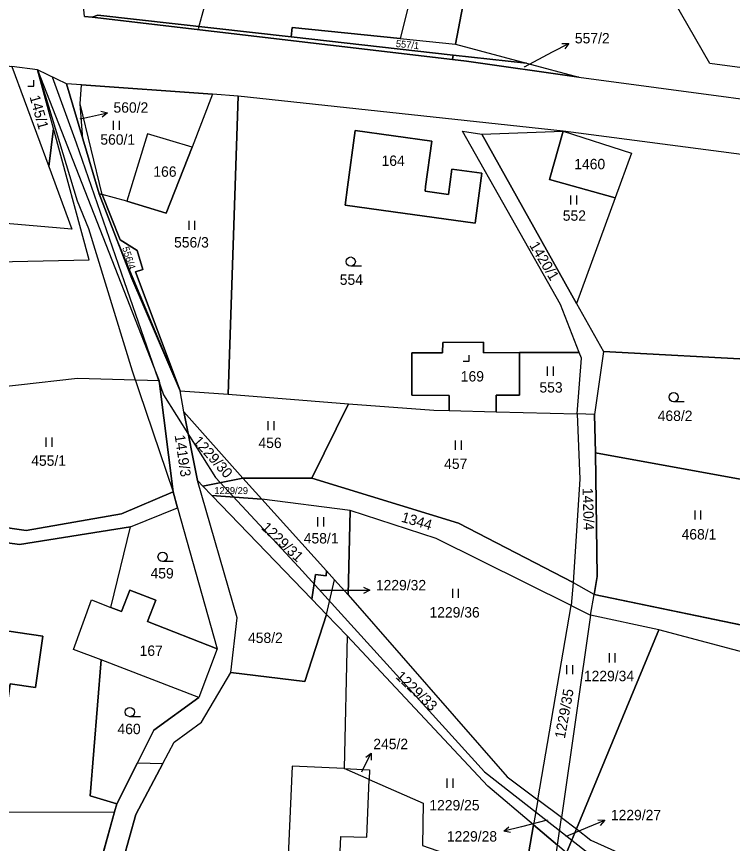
# Model space of a CAD drawing. Extents: x -588699 to -585793, y -1060280 to -1056731.
# Drawn here: x -586946 to -586828.9, y -1058685.8 to -1058550.5 of the extents above; entities that cross this region are included whole.
import ezdxf

# ---------------------------------------------------------------- set-up
doc = ezdxf.new("R2010")
doc.units = 0
for name, color, linetype in [('Druh pozemku', 7, 'Continuous'), ('Lesy', 7, 'Continuous'), ('Parcela nároku', 7, 'Continuous'), ('Parcelní číslo', 7, 'Continuous'), ('Vnitřní obvod', 7, 'Continuous')]:
    doc.layers.add(name, color=color, linetype=linetype)

msp = doc.modelspace()

# ---------------------------------------------------------------- linework, layer by layer
at = {"layer": 'Druh pozemku'}
for p, q in [((-586930.2, -1058567.55), (-586930.2, -1058569.05)), ((-586929.18, -1058569.05), (-586929.18, -1058567.55)), ((-586855.37, -1058579.77), (-586855.37, -1058581.27)), ((-586854.34, -1058581.27), (-586854.34, -1058579.77)), ((-586917.83, -1058583.91), (-586917.83, -1058585.41)), ((-586916.81, -1058585.41), (-586916.81, -1058583.91)), ((-586889.57, -1058591.35), (-586891.32, -1058591.35)), ((-586859.16, -1058607.79), (-586859.16, -1058609.29)), ((-586858.14, -1058609.29), (-586858.14, -1058607.79)), ((-586836.75, -1058613.54), (-586838.5, -1058613.54)), ((-586904.89, -1058616.72), (-586904.89, -1058618.22)), ((-586903.86, -1058618.22), (-586903.86, -1058616.72)), ((-586941.23, -1058619.41), (-586941.23, -1058620.91)), ((-586940.2, -1058620.91), (-586940.2, -1058619.41)), ((-586874.25, -1058619.9), (-586874.25, -1058621.4)), ((-586873.22, -1058621.4), (-586873.22, -1058619.9)), ((-586835.04, -1058631.34), (-586835.04, -1058632.84)), ((-586834.02, -1058632.84), (-586834.02, -1058631.34)), ((-586896.77, -1058632.46), (-586896.77, -1058633.96)), ((-586895.74, -1058633.96), (-586895.74, -1058632.46)), ((-586920.36, -1058639.67), (-586922.11, -1058639.67)), ((-586874.7, -1058644.16), (-586874.7, -1058645.66)), ((-586873.68, -1058645.66), (-586873.68, -1058644.16)), ((-586849.06, -1058654.71), (-586849.06, -1058656.21)), ((-586848.04, -1058656.21), (-586848.04, -1058654.71)), ((-586856.01, -1058656.65), (-586856.01, -1058658.15)), ((-586854.98, -1058658.15), (-586854.98, -1058656.65)), ((-586925.72, -1058665.09), (-586927.47, -1058665.09)), ((-586875.6, -1058675.22), (-586875.6, -1058676.72)), ((-586874.58, -1058676.72), (-586874.58, -1058675.22))]:
    msp.add_line(p, q, dxfattribs=at)
for points in [[(-586944.16, -1058561.89), (-586943.16, -1058561.89), (-586943.16, -1058560.89)], [(-586872.92, -1058606.9), (-586871.92, -1058606.9), (-586871.92, -1058605.9)]]:
    msp.add_lwpolyline(points, dxfattribs=at)
for centre in [(-586891.32, -1058590.6), (-586838.5, -1058612.79), (-586922.11, -1058638.92), (-586927.47, -1058664.34)]:
    msp.add_circle(centre, 0.75, dxfattribs=at)
at = {"layer": 'Lesy'}
for p, q in [((-586937.84, -1058561.49), (-586942.57, -1058559.22)), ((-586932.48, -1058579.51), (-586935.16, -1058570.5)), ((-586929.81, -1058586.43), (-586932.48, -1058579.51)), ((-586934.24, -1058585.2), (-586927.07, -1058608.49)), ((-586919.25, -1058611.77), (-586929.81, -1058586.43)), ((-586927.07, -1058608.49), (-586920.38, -1058628.31)), ((-586918.62, -1058615.19), (-586919.25, -1058611.77)), ((-586909, -1058626.06), (-586918.62, -1058615.19)), ((-586897.7, -1058626.06), (-586909, -1058626.06)), ((-586873.71, -1058633.44), (-586897.7, -1058626.06)), ((-586920.38, -1058628.31), (-586919.65, -1058630.91)), ((-586919.65, -1058630.91), (-586913.16, -1058653.98)), ((-586855.25, -1058642.98), (-586873.71, -1058633.44)), ((-586851.48, -1058645.09), (-586855.25, -1058642.98)), ((-586817.65, -1058652.11), (-586851.48, -1058645.09)), ((-586913.16, -1058653.98), (-586916.18, -1058661.96)), ((-586916.18, -1058661.96), (-586923.52, -1058667.3)), ((-586923.52, -1058667.3), (-586926.22, -1058672.66)), ((-586926.22, -1058672.66), (-586929.59, -1058679.33)), ((-586929.59, -1058679.33), (-586929.95, -1058680.64)), ((-586929.95, -1058680.64), (-586935.97, -1058702.25))]:
    msp.add_line(p, q, dxfattribs=at)
for points in [[(-586942.57, -1058559.22), (-586936.11, -1058580.67), (-586934.24, -1058585.2)], [(-586935.16, -1058570.5), (-586935.57, -1058564.8), (-586935.4, -1058561.66), (-586937.84, -1058561.49)]]:
    msp.add_lwpolyline(points, dxfattribs=at)
at = {"layer": 'Parcela nároku'}
for points in [[(-586935.39, -1058545.43), (-586930.16, -1058501.68), (-586916.68, -1058504.17), (-586904.54, -1058509.26), (-586892.17, -1058517.22), (-586875.35, -1058522.58), (-586883.25, -1058554.1), (-586900.89, -1058552.29), (-586901.09, -1058553.82), (-586932.71, -1058550.27), (-586933.62, -1058550.62), (-586934.89, -1058550.47)], [(-586869.14, -1058528.69), (-586875.35, -1058522.58), (-586883.25, -1058554.1), (-586874.19, -1058555.03)], [(-586871.4, -1058523.77), (-586875.35, -1058522.58), (-586869.14, -1058528.69), (-586874.19, -1058555.03), (-586862.54, -1058558.15), (-586854.02, -1058560.42), (-586804.23, -1058567.06), (-586807.28, -1058561.54), (-586832.56, -1058558.16), (-586845.52, -1058535.63), (-586863.45, -1058526.16)], [(-586845.52, -1058535.63), (-586838.02, -1058539.59), (-586814.5, -1058548.51), (-586807.28, -1058561.54), (-586832.56, -1058558.16)], [(-586901.09, -1058553.82), (-586874.54, -1058556.8), (-586874.68, -1058557.5), (-586933.62, -1058550.62), (-586932.71, -1058550.27)], [(-586883.25, -1058554.1), (-586874.19, -1058555.03), (-586862.54, -1058558.15), (-586874.54, -1058556.8), (-586901.09, -1058553.82), (-586900.89, -1058552.29)], [(-586982.64, -1058555.63), (-586983.76, -1058577.52), (-586984.31, -1058591.39), (-586934.1, -1058590.3), (-586939.95, -1058568.84), (-586940.74, -1058575.03), (-586936.96, -1058585.27), (-586967.4, -1058582.66), (-586965.22, -1058556.24), (-586979.1, -1058554.41)], [(-586940.74, -1058575.03), (-586936.96, -1058585.27), (-586967.4, -1058582.66), (-586965.22, -1058556.24), (-586946.78, -1058558.67)], [(-586874.54, -1058556.8), (-586862.54, -1058558.15), (-586854.02, -1058560.42), (-586872.37, -1058557.77), (-586874.68, -1058557.5)], [(-586996.63, -1058616.02), (-586984.31, -1058591.39), (-586934.1, -1058590.3), (-586939.95, -1058568.84), (-586942.57, -1058559.22), (-586922.66, -1058610.11), (-586936.01, -1058609.72), (-586955.38, -1058611.93), (-586955.53, -1058604.84), (-586975.52, -1058605.27), (-586975.17, -1058621.7), (-586987.28, -1058624.4)], [(-586939.95, -1058568.84), (-586942.57, -1058559.22), (-586946.78, -1058558.67), (-586940.74, -1058575.03)], [(-586937.84, -1058561.49), (-586942.57, -1058559.22), (-586922.66, -1058610.11), (-586920.38, -1058628.31), (-586919.65, -1058630.91), (-586913.16, -1058653.98), (-586916.18, -1058661.96), (-586923.52, -1058667.3), (-586926.22, -1058672.66), (-586922.07, -1058672.74), (-586920.21, -1058669.24), (-586915.73, -1058666.01), (-586910.92, -1058657.87), (-586909.93, -1058648.91), (-586916.41, -1058626.46), (-586918.62, -1058615.19), (-586919.25, -1058611.77), (-586927.14, -1058593.35), (-586932.48, -1058579.51)], [(-586931.97, -1058579.64), (-586935.57, -1058564.8), (-586935.4, -1058561.66), (-586937.84, -1058561.49), (-586932.48, -1058579.51)], [(-586935.57, -1058564.8), (-586935.4, -1058561.66), (-586913.94, -1058563.18), (-586917.29, -1058571.85), (-586924.56, -1058569.67), (-586927.97, -1058580.71), (-586931.97, -1058579.64)], [(-586909.75, -1058563.5), (-586913.94, -1058563.18), (-586917.29, -1058571.85), (-586921.5, -1058582.69), (-586927.97, -1058580.71), (-586931.97, -1058579.64), (-586929.05, -1058587.03), (-586926.29, -1058588.8), (-586925.34, -1058591.91), (-586926.52, -1058592.27), (-586919.25, -1058611.77), (-586911.39, -1058612.32)], [(-586881.31, -1058612.49), (-586881.32, -1058605.54), (-586876.29, -1058605.53), (-586876.28, -1058603.82), (-586869.61, -1058603.81), (-586869.61, -1058605.51), (-586863.69, -1058605.5), (-586853.93, -1058605.48), (-586857.02, -1058597.61), (-586873.05, -1058569.24), (-586869.85, -1058569.74), (-586856.59, -1058569.23), (-586909.75, -1058563.5), (-586911.39, -1058612.32), (-586891.71, -1058613.89), (-586877.73, -1058614.93), (-586875.22, -1058614.99), (-586875.23, -1058612.52)], [(-586891.86, -1058578.43), (-586890.62, -1058569.15), (-586878.07, -1058570.88), (-586879.09, -1058578.3), (-586879.17, -1058579.09), (-586875.33, -1058579.6), (-586874.78, -1058575.49), (-586869.86, -1058576.15), (-586870.95, -1058584.3), (-586884.39, -1058582.45), (-586892.23, -1058581.36)], [(-586870.95, -1058584.3), (-586869.86, -1058576.15), (-586874.78, -1058575.49), (-586875.33, -1058579.6), (-586879.17, -1058579.09), (-586879.09, -1058578.3), (-586878.07, -1058570.88), (-586890.62, -1058569.15), (-586891.86, -1058578.43), (-586892.23, -1058581.36), (-586884.39, -1058582.45)], [(-586917.29, -1058571.85), (-586924.56, -1058569.67), (-586927.97, -1058580.71), (-586921.5, -1058582.69)], [(-586854.25, -1058615.51), (-586853.56, -1058606.42), (-586853.93, -1058605.48), (-586857.02, -1058597.61), (-586873.05, -1058569.24), (-586869.85, -1058569.74), (-586854.38, -1058597.45), (-586849.98, -1058605.33), (-586851.42, -1058615.61)], [(-586858.8, -1058577.17), (-586848.05, -1058580.18), (-586854.38, -1058597.45), (-586869.85, -1058569.74), (-586856.59, -1058569.23)], [(-586856.59, -1058569.23), (-586845.36, -1058572.84), (-586848.05, -1058580.18), (-586858.8, -1058577.17)], [(-586848.05, -1058580.18), (-586854.38, -1058597.45), (-586849.98, -1058605.33), (-586823.61, -1058606.72), (-586816.91, -1058607.07), (-586816.4, -1058604.52), (-586811.36, -1058605.37), (-586811.07, -1058603.41), (-586802.46, -1058605.29), (-586803.06, -1058608.62), (-586800.23, -1058609.18), (-586797.12, -1058609.8), (-586796.17, -1058600.31), (-586795.7, -1058577.24), (-586856.59, -1058569.23), (-586845.36, -1058572.84)], [(-586919.25, -1058611.77), (-586926.52, -1058592.27), (-586925.34, -1058591.91), (-586926.29, -1058588.8), (-586929.05, -1058587.03), (-586931.97, -1058579.64), (-586932.48, -1058579.51), (-586927.14, -1058593.35)], [(-586876.29, -1058605.53), (-586881.32, -1058605.54), (-586881.31, -1058612.49), (-586875.23, -1058612.52), (-586875.22, -1058614.99), (-586867.52, -1058615.18), (-586867.54, -1058612.49), (-586863.69, -1058612.49), (-586863.69, -1058605.5), (-586869.61, -1058605.51), (-586869.61, -1058603.81), (-586876.28, -1058603.82)], [(-586863.69, -1058612.49), (-586867.54, -1058612.49), (-586867.52, -1058615.18), (-586854.25, -1058615.51), (-586853.56, -1058606.42), (-586853.93, -1058605.48), (-586863.69, -1058605.5)], [(-586823.61, -1058606.72), (-586849.98, -1058605.33), (-586851.42, -1058615.61), (-586851.29, -1058621.89), (-586822.19, -1058627.19), (-586821.69, -1058624.31), (-586810.47, -1058626.19), (-586810.97, -1058629.24), (-586800.47, -1058631.15), (-586798.62, -1058625.12), (-586825.01, -1058620.48)], [(-586955.1, -1058624.84), (-586975.09, -1058625.27), (-586975.17, -1058621.7), (-586987.28, -1058624.4), (-586974.32, -1058630.3), (-586944.43, -1058634.63), (-586928.81, -1058631.9), (-586920.38, -1058628.31), (-586922.66, -1058610.11), (-586936.01, -1058609.72), (-586955.38, -1058611.93)], [(-586911.39, -1058612.32), (-586891.71, -1058613.89), (-586897.7, -1058626.06), (-586909, -1058626.06), (-586918.62, -1058615.19), (-586919.25, -1058611.77)], [(-586909, -1058626.06), (-586918.62, -1058615.19), (-586916.41, -1058626.46), (-586915.52, -1058627.37)], [(-586891.71, -1058613.89), (-586877.73, -1058614.93), (-586875.22, -1058614.99), (-586867.52, -1058615.18), (-586854.25, -1058615.51), (-586853.82, -1058626.21), (-586854.92, -1058643.12), (-586873.71, -1058633.44), (-586897.7, -1058626.06)], [(-586944.43, -1058634.63), (-586974.32, -1058630.3), (-586987.28, -1058624.4), (-586996.63, -1058616.02), (-586997.71, -1058618.13), (-586988.17, -1058626.9), (-586973.23, -1058633.1), (-586945.54, -1058636.92), (-586927.38, -1058634.01), (-586919.65, -1058630.91), (-586920.38, -1058628.31), (-586928.81, -1058631.9)], [(-586851.29, -1058621.89), (-586851.42, -1058615.61), (-586854.25, -1058615.51), (-586853.82, -1058626.21), (-586854.92, -1058643.12), (-586855.24, -1058646.91), (-586852.11, -1058648.46), (-586851.48, -1058645.09), (-586851.01, -1058642.14)], [(-586822.19, -1058627.19), (-586851.29, -1058621.89), (-586851.01, -1058642.14), (-586851.48, -1058645.09), (-586817.65, -1058652.11), (-586805.15, -1058658.88), (-586801.97, -1058646.29), (-586801.14, -1058637.92), (-586800.47, -1058631.15), (-586810.97, -1058629.24), (-586812.33, -1058637.49), (-586818.79, -1058636.38), (-586817.95, -1058631.53), (-586822.8, -1058630.72)], [(-586897.67, -1058645.88), (-586895.29, -1058648.35), (-586898.83, -1058659.35), (-586910.92, -1058657.87), (-586909.93, -1058648.91), (-586916.41, -1058626.46), (-586915.52, -1058627.37), (-586914.05, -1058628.88)], [(-586905.89, -1058629.51), (-586909, -1058626.06), (-586915.52, -1058627.37), (-586914.05, -1058628.88)], [(-586897.7, -1058626.06), (-586873.71, -1058633.44), (-586854.92, -1058643.12), (-586855.24, -1058646.91), (-586877.37, -1058635.92), (-586891.44, -1058631.37), (-586905.89, -1058629.51), (-586909, -1058626.06)], [(-586895.31, -1058641.23), (-586905.89, -1058629.51), (-586914.05, -1058628.88), (-586897.67, -1058645.88), (-586897.09, -1058641.82), (-586895.37, -1058642.04)], [(-586891.44, -1058631.37), (-586905.89, -1058629.51), (-586895.31, -1058641.23), (-586893.99, -1058642.68), (-586891.75, -1058645.16)], [(-586924.55, -1058649.53), (-586923.22, -1058646.04), (-586927.48, -1058644.38), (-586928.82, -1058647.87), (-586930.55, -1058647.2), (-586927.38, -1058634.01), (-586919.65, -1058630.91), (-586913.16, -1058653.98)], [(-586877.37, -1058635.92), (-586891.44, -1058631.37), (-586891.75, -1058645.16), (-586865.74, -1058674.93), (-586860.73, -1058678.68), (-586855.24, -1058646.91)], [(-586932.16, -1058655.81), (-586936.67, -1058654.08), (-586933.73, -1058645.96), (-586930.55, -1058647.2), (-586927.38, -1058634.01), (-586945.54, -1058636.92), (-586973.23, -1058633.1), (-586982.68, -1058632.84), (-586977.96, -1058666.11), (-586973.22, -1058680.8), (-586929.95, -1058680.64), (-586929.59, -1058679.33), (-586933.94, -1058678.03)], [(-586895.31, -1058641.23), (-586895.37, -1058642.04), (-586897.09, -1058641.82), (-586897.67, -1058645.88), (-586895.29, -1058648.35), (-586893.99, -1058642.68)], [(-586893.99, -1058642.68), (-586891.75, -1058645.16), (-586865.74, -1058674.93), (-586860.73, -1058678.68), (-586861.44, -1058682.79), (-586868.9, -1058676.45), (-586891.9, -1058651.87), (-586895.29, -1058648.35)], [(-586933.73, -1058645.96), (-586930.55, -1058647.2), (-586928.82, -1058647.87), (-586927.48, -1058644.38), (-586923.22, -1058646.04), (-586924.55, -1058649.53), (-586913.16, -1058653.98), (-586916.18, -1058661.96), (-586932.16, -1058655.81), (-586936.67, -1058654.08)], [(-586851.48, -1058645.09), (-586817.65, -1058652.11), (-586805.15, -1058658.88), (-586791.48, -1058671.6), (-586792.77, -1058674.76), (-586796.81, -1058672.17), (-586805.63, -1058662.11), (-586816.72, -1058657.34), (-586840.89, -1058650.86), (-586852.11, -1058648.46)], [(-586855.24, -1058646.91), (-586852.11, -1058648.46), (-586856.86, -1058681.59), (-586860.73, -1058678.68)], [(-586840.89, -1058650.86), (-586852.11, -1058648.46), (-586856.86, -1058681.59), (-586854.39, -1058683.44)], [(-586945.81, -1058651.29), (-586941.68, -1058651.91), (-586942.92, -1058660.31), (-586947.04, -1058659.71), (-586948.86, -1058672.19), (-586958.77, -1058670.94), (-586955.67, -1058649.84)], [(-586958.77, -1058670.94), (-586948.86, -1058672.19), (-586947.04, -1058659.71), (-586942.92, -1058660.31), (-586941.68, -1058651.91), (-586945.81, -1058651.29), (-586955.67, -1058649.84)], [(-586805.63, -1058662.11), (-586816.72, -1058657.34), (-586840.89, -1058650.86), (-586854.39, -1058683.44), (-586852.02, -1058685.29), (-586820.88, -1058699.32), (-586805.39, -1058705.78), (-586803.87, -1058706.44), (-586802.96, -1058699.63), (-586799.98, -1058686.35), (-586796.81, -1058672.17)], [(-586868.9, -1058676.45), (-586891.9, -1058651.87), (-586892.4, -1058673.58), (-586888.23, -1058673.81), (-586888.3, -1058675.38), (-586879.46, -1058679.27), (-586879.6, -1058686.15), (-586863.03, -1058691.98), (-586861.44, -1058682.79)], [(-586916.18, -1058661.96), (-586932.16, -1058655.81), (-586933.94, -1058678.03), (-586929.59, -1058679.33), (-586926.22, -1058672.66), (-586923.52, -1058667.3)], [(-586938.93, -1058736.17), (-586935.97, -1058702.25), (-586929.95, -1058680.64), (-586929.59, -1058679.33), (-586926.22, -1058672.66), (-586922.07, -1058672.74), (-586926.49, -1058681.08), (-586932.68, -1058703.36), (-586934.27, -1058720.98), (-586935.76, -1058737.71), (-586941.82, -1058775.73), (-586945.72, -1058787.88), (-586948.79, -1058785.05), (-586945.33, -1058774.96)], [(-586903.15, -1058691.48), (-586903.25, -1058693.43), (-586901.8, -1058693.5), (-586903.2, -1058722.75), (-586894.83, -1058723.27), (-586893.4, -1058694), (-586891.88, -1058693.96), (-586891.79, -1058692.15), (-586893.26, -1058692.06), (-586892.92, -1058684.68), (-586888.69, -1058684.79), (-586888.3, -1058675.38), (-586892.4, -1058673.58), (-586900.9, -1058673.18), (-586901.71, -1058691.55)], [(-586892.4, -1058673.58), (-586888.23, -1058673.81), (-586888.3, -1058675.38)], [(-586860.73, -1058678.68), (-586861.44, -1058682.79), (-586857.51, -1058686.13), (-586856.86, -1058681.59)], [(-586973.22, -1058680.8), (-586929.95, -1058680.64), (-586935.97, -1058702.25), (-586938.93, -1058736.17), (-586955.56, -1058735.53)], [(-586861.44, -1058682.79), (-586863.03, -1058691.98), (-586858.58, -1058693.54), (-586857.51, -1058686.13)], [(-586857.51, -1058686.13), (-586856.86, -1058681.59), (-586854.39, -1058683.44), (-586856.03, -1058687.39)], [(-586854.39, -1058683.44), (-586852.02, -1058685.29), (-586820.88, -1058699.32), (-586805.39, -1058705.78), (-586803.87, -1058706.44), (-586804.7, -1058712.59), (-586808.72, -1058710.56), (-586853.81, -1058689.27), (-586856.03, -1058687.39)]]:
    msp.add_lwpolyline(points, close=True, dxfattribs=at)
for points in [[(-586934.89, -1058550.47), (-586933.62, -1058550.62), (-586874.68, -1058557.5), (-586872.37, -1058557.77), (-586854.02, -1058560.42), (-586804.23, -1058567.06), (-586803.05, -1058567.22), (-586798.16, -1058567.87), (-586687.14, -1058583.77), (-586665.54, -1058591.33), (-586602.99, -1058626.52)], [(-586618.94, -1058628.76), (-586660.99, -1058605.82), (-586679.22, -1058595.88), (-586690.29, -1058590.65), (-586705.65, -1058589.53), (-586716.68, -1058588.73), (-586716.99, -1058590.88), (-586735.61, -1058587.36), (-586740.23, -1058586.48), (-586755.16, -1058583.44), (-586759.61, -1058582.79), (-586774.79, -1058579.98), (-586795.7, -1058577.24), (-586856.59, -1058569.23), (-586909.75, -1058563.5), (-586913.94, -1058563.18), (-586935.4, -1058561.66), (-586937.84, -1058561.49), (-586942.57, -1058559.22), (-586946.78, -1058558.67)], [(-586932.68, -1058703.36), (-586926.49, -1058681.08), (-586922.07, -1058672.74), (-586920.21, -1058669.24), (-586915.73, -1058666.01), (-586910.92, -1058657.87), (-586898.83, -1058659.35), (-586895.29, -1058648.35), (-586891.9, -1058651.87), (-586892.4, -1058673.58), (-586900.9, -1058673.18), (-586901.71, -1058691.55)], [(-586893.26, -1058692.06), (-586892.92, -1058684.68), (-586888.69, -1058684.79), (-586888.3, -1058675.38), (-586879.46, -1058679.27), (-586879.6, -1058686.15)]]:
    msp.add_lwpolyline(points, dxfattribs=at)
at = {"layer": 'Parcelní číslo'}
for p, q in [((-586916.21, -1058552.46), (-586915.3, -1058549.05)), ((-586858.3, -1058556.29), (-586855.65, -1058554.89)), ((-586862.87, -1058558.71), (-586858.3, -1058556.29)), ((-586934.06, -1058566.9), (-586931.14, -1058566.23)), ((-586935.58, -1058567.25), (-586934.06, -1058566.9)), ((-586896.2, -1058644.41), (-586891.21, -1058644.41)), ((-586891.21, -1058644.41), (-586888.21, -1058644.41)), ((-586889.34, -1058673.75), (-586887.97, -1058671.08)), ((-586889.52, -1058674.11), (-586889.34, -1058673.75)), ((-586859.18, -1058682.04), (-586863.39, -1058683.1)), ((-586852.53, -1058683.2), (-586849.76, -1058682.04)), ((-586863.39, -1058683.1), (-586866.3, -1058683.83)), ((-586856.04, -1058684.67), (-586852.53, -1058683.2))]:
    msp.add_line(p, q, dxfattribs=at)
for points in [[(-586856.77, -1058554.91), (-586855.65, -1058554.89), (-586856.3, -1058555.8)], [(-586932.22, -1058565.96), (-586931.14, -1058566.23), (-586932, -1058566.94)], [(-586889.21, -1058643.91), (-586888.21, -1058644.41), (-586889.21, -1058644.91)], [(-586888.87, -1058671.74), (-586887.97, -1058671.08), (-586887.98, -1058672.2)], [(-586850.88, -1058681.97), (-586849.76, -1058682.04), (-586850.49, -1058682.89)], [(-586865.21, -1058684.07), (-586866.3, -1058683.83), (-586865.45, -1058683.1)]]:
    msp.add_lwpolyline(points, dxfattribs=at)
at = {"layer": 'Vnitřní obvod'}
msp.add_lwpolyline([(-586940.2, -1058560.36), (-586936.24, -1058571.16), (-586928.38, -1058593.88), (-586921.96, -1058612.43), (-586913.44, -1058625.95), (-586899.8, -1058640.6), (-586869.43, -1058674.12), (-586852.91, -1058687.06), (-586801.12, -1058710.38)], dxfattribs=at)

# ---------------------------------------------------------------- texts
at = {"layer": 'Parcela nároku'}
for s, height, p in [('587/2', 0.1, (-586916.39, -1058552.46)), ('557/2', 0.1, (-586863.05, -1058558.71)), ('560/2', 0.1, (-586935.77, -1058567.25)), ('560/1', 1.7, (-586932.29, -1058571.47)), ('164', 1.7, (-586886.28, -1058574.94)), ('1460', 1.7, (-586854.75, -1058575.49)), ('166', 1.7, (-586923.62, -1058576.72)), ('552', 1.7, (-586856.63, -1058583.92)), ('556/3', 1.7, (-586920.23, -1058588.3)), ('554', 1.7, (-586893.12, -1058594.41)), ('169', 1.7, (-586873.32, -1058610.23)), ('553', 1.7, (-586860.45, -1058612.04)), ('468/2', 1.7, (-586841.1, -1058616.69)), ('456', 1.7, (-586906.42, -1058621.12)), ('455/1', 1.7, (-586943.6, -1058624.03)), ('457', 1.7, (-586876.04, -1058624.54)), ('1229/29', 1.14, (-586913.64, -1058628.66)), ('458/1', 1.7, (-586899.01, -1058636.74)), ('468/1', 1.7, (-586837.19, -1058636.09)), ('459', 1.7, (-586924.08, -1058642.47)), ('1229/32', 0.1, (-586896.45, -1058644.41)), ('1229/36', 1.7, (-586878.44, -1058648.86)), ('458/2', 1.7, (-586908.13, -1058653.03)), ('167', 1.7, (-586925.86, -1058655.14)), ('1229/34', 1.7, (-586853.18, -1058659.28)), ('460', 1.7, (-586929.49, -1058667.95)), ('245/2', 0.1, (-586889.52, -1058674.11)), ('1229/25', 1.7, (-586878.46, -1058680.43)), ('1229/28', 0.1, (-586859.42, -1058682.04)), ('1229/27', 0.1, (-586856.28, -1058684.67))]:
    msp.add_text(s, height=height, dxfattribs=at).set_placement(p)
for s, height, rotation, p in [('557/1', 1.14, 354.1729, (-586883.99, -1058555.47)), ('145/1', 1.7, 285.736, (-586943.89, -1058563.63)), ('556/4', 1.14, 287.4521, (-586928.73, -1058588.35)), ('1420/1', 1.7, 300.8077, (-586862.16, -1058587.93)), ('1419/3', 1.7, 278.3749, (-586920.14, -1058619.06)), ('1229/30', 1.7, 311.8777, (-586917.25, -1058620.08)), ('1420/4', 1.7, 271.8462, (-586853.41, -1058627.67)), ('1344', 1.7, 343.398, (-586883.17, -1058633.15)), ('1229/31', 1.7, 316.945, (-586906.07, -1058634.29)), ('1229/33', 1.7, 316.6989, (-586884.12, -1058658.67)), ('1229/35', 1.7, 79.7267, (-586856.3, -1058668.78))]:
    msp.add_text(s, height=height, rotation=rotation, dxfattribs=at).set_placement(p)
at = {"layer": 'Parcelní číslo'}
for s, p in [('557/2', (-586854.65, -1058554.89)), ('560/2', (-586930.14, -1058566.23)), ('1229/32', (-586887.21, -1058644.41)), ('245/2', (-586887.63, -1058670.41)), ('1229/27', (-586848.76, -1058682.04)), ('1229/28', (-586875.6, -1058685.53))]:
    msp.add_text(s, height=1.7, dxfattribs=at).set_placement(p)

doc.saveas('drawing.dxf')
